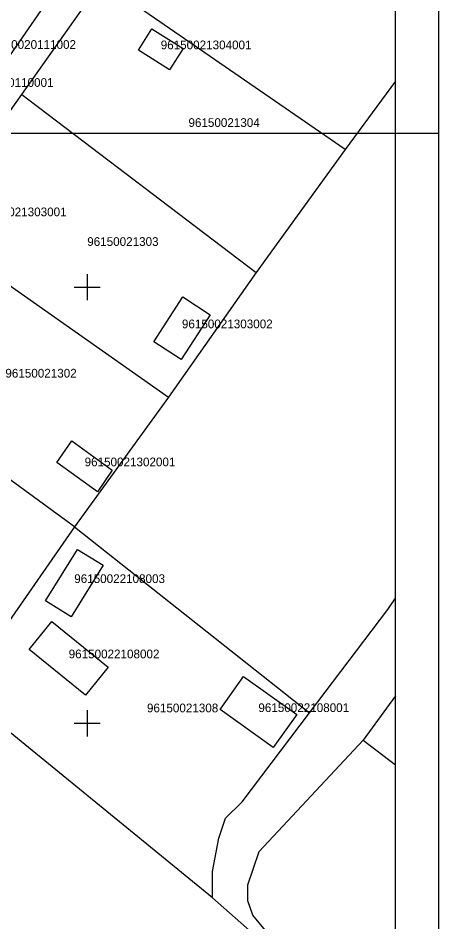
# Model space of a CAD drawing. Extents: x 578395 to 578590, y 418519 to 418816.
# Drawn here: x 578542.1 to 578590.4, y 418577.2 to 418680.8 of the extents above; entities that cross this region are included whole.
import ezdxf

# ---------------------------------------------------------------- set-up
doc = ezdxf.new("R2010")
doc.units = 0
for name, color, linetype in [('BUVE_EKAS_UZMR_####_#', 7, 'Continuous'), ('BUVE_EKAS_UZMR_TKST_#', 7, 'Continuous'), ('BUVE_EKAS_VEKT_####_#', 7, 'Continuous'), ('BUVE_EKAS_VEKT_TKST_#', 7, 'Continuous'), ('GEOD_ELEM_####_####_#', 7, 'Continuous'), ('RAMI_PLAN_####_TKST_#', 7, 'Continuous'), ('ROBZ_PROJ_####_####_#', 7, 'Continuous'), ('ROBZ_PROJ_####_TKST_#', 7, 'Continuous'), ('ROBZ_UZMR_####_####_#', 7, 'Continuous'), ('ROBZ_UZMR_####_TKST_#', 7, 'Continuous')]:
    doc.layers.add(name, color=color, linetype=linetype)

msp = doc.modelspace()

# ---------------------------------------------------------------- linework, layer by layer
at = {"layer": 'BUVE_EKAS_UZMR_####_#'}
for p, q in [((578546.54, 418629.91), (578548.25, 418632.38)), ((578548.25, 418632.38), (578552.88, 418629.01)), ((578551.17, 418626.54), (578546.54, 418629.91)), ((578552.88, 418629.01), (578551.17, 418626.54))]:
    msp.add_line(p, q, dxfattribs=at)
at = {"layer": 'BUVE_EKAS_VEKT_####_#'}
for p, q in [((578555.88, 418677.17), (578557.42, 418679.61)), ((578557.42, 418679.61), (578561, 418677.35)), ((578561, 418677.35), (578559.46, 418674.91)), ((578559.46, 418674.91), (578555.88, 418677.17)), ((578557.64, 418643.73), (578560.96, 418648.87)), ((578560.96, 418648.87), (578564.11, 418646.83)), ((578564.11, 418646.83), (578560.79, 418641.69)), ((578560.79, 418641.69), (578557.64, 418643.73)), ((578545.23, 418614.04), (578548.89, 418619.94)), ((578548.89, 418619.94), (578551.82, 418618.12)), ((578551.82, 418618.12), (578548.15, 418612.22)), ((578548.15, 418612.22), (578545.23, 418614.04)), ((578543.34, 418608.46), (578545.95, 418611.67)), ((578545.95, 418611.67), (578552.41, 418606.43)), ((578549.81, 418603.22), (578543.34, 418608.46)), ((578552.41, 418606.43), (578549.81, 418603.22)), ((578565.24, 418601.57), (578567.95, 418605.37)), ((578567.95, 418605.37), (578574.05, 418601.01)), ((578571.33, 418597.21), (578565.24, 418601.57)), ((578574.05, 418601.01), (578571.33, 418597.21))]:
    msp.add_line(p, q, dxfattribs=at)
at = {"layer": 'GEOD_ELEM_####_####_#'}
for p, q in [((578550, 418651.5), (578550, 418650)), ((578548.5, 418650), (578550, 418650)), ((578550, 418650), (578550, 418648.5)), ((578550, 418650), (578551.5, 418650)), ((578550, 418601.5), (578550, 418600)), ((578548.5, 418600), (578550, 418600)), ((578550, 418600), (578550, 418598.5)), ((578550, 418600), (578551.5, 418600))]:
    msp.add_line(p, q, dxfattribs=at)
at = {"layer": 'RAMI_PLAN_####_TKST_#'}
for p, q in [((578590.35, 418667.61), (578590.35, 418816.11)), ((578590.35, 418667.61), (578395.35, 418667.61)), ((578590.35, 418519.11), (578590.35, 418667.61))]:
    msp.add_line(p, q, dxfattribs=at)
msp.add_lwpolyline([(578410.35, 418811.11), (578410.35, 418524.11), (578585.35, 418524.11), (578585.35, 418811.11)], close=True, dxfattribs=at)
at = {"layer": 'ROBZ_PROJ_####_####_#'}
for p, q in [((578542.49, 418672.06), (578551.67, 418685.02)), ((578539.59, 418667.97), (578542.49, 418672.06)), ((578542.49, 418672.06), (578569.4, 418651.69)), ((578579.6, 418665.77), (578569.4, 418651.69)), ((578569.4, 418651.69), (578559.32, 418637.39)), ((578548.55, 418622.53), (578535.41, 418603.64)), ((578548.55, 418622.53), (578575.5, 418601.19)), ((578584.48, 418613.04), (578585.35, 418614.35)), ((578575.5, 418601.19), (578584.48, 418613.04)), ((578564.36, 418579.99), (578535.41, 418603.64)), ((578585.35, 418603.15), (578581.65, 418598.05)), ((578567.77, 418591.01), (578575.5, 418601.19)), ((578569.72, 418585.29), (578581.65, 418598.05)), ((578581.65, 418598.05), (578585.35, 418595.24)), ((578565.88, 418589.11), (578567.77, 418591.01)), ((578565.12, 418586.83), (578565.88, 418589.11)), ((578564.36, 418583.03), (578565.12, 418586.83)), ((578568.45, 418581.47), (578569.72, 418585.29)), ((578564.36, 418579.99), (578564.36, 418583.03)), ((578568.45, 418579.66), (578568.45, 418581.47)), ((578572.45, 418572.93), (578564.36, 418579.99)), ((578569, 418578.02), (578568.45, 418579.66)), ((578570.63, 418576.02), (578569, 418578.02))]:
    msp.add_line(p, q, dxfattribs=at)
at = {"layer": 'ROBZ_UZMR_####_####_#'}
for p, q in [((578548.65, 418687.44), (578538.85, 418673.28)), ((578579.6, 418665.77), (578551.67, 418685.02)), ((578585.35, 418673.6), (578579.6, 418665.77)), ((578531.78, 418656.72), (578559.32, 418637.39)), ((578548.55, 418622.53), (578521.46, 418642.29)), ((578559.32, 418637.39), (578548.55, 418622.53))]:
    msp.add_line(p, q, dxfattribs=at)

# ---------------------------------------------------------------- texts
at = {"layer": 'BUVE_EKAS_UZMR_TKST_#'}
for s, p in [('96150020110001', (578535.73, 418672.95)), ('96150021302001', (578549.71, 418629.46))]:
    msp.add_text(s, height=1, dxfattribs=at).set_placement(p)
at = {"layer": 'BUVE_EKAS_VEKT_TKST_#'}
for s, p in [('96150020111002', (578538.31, 418677.31)), ('96150021304001', (578558.44, 418677.26)), ('96150021303001', (578537.23, 418658.12)), ('96150021303002', (578560.87, 418645.28)), ('96150022108003', (578548.52, 418616.08)), ('96150022108002', (578547.88, 418607.45)), ('96150022108001', (578569.64, 418601.29))]:
    msp.add_text(s, height=1, dxfattribs=at).set_placement(p)
at = {"layer": 'ROBZ_PROJ_####_TKST_#'}
for s, p in [('96150021304', (578561.62, 418668.36)), ('96150021303', (578550.01, 418654.72)), ('96150021308', (578556.86, 418601.26))]:
    msp.add_text(s, height=1, dxfattribs=at).set_placement(p)
at = {"layer": 'ROBZ_UZMR_####_TKST_#'}
msp.add_text('96150021302', height=1, dxfattribs=at).set_placement((578540.62, 418639.63))

doc.saveas('drawing.dxf')
